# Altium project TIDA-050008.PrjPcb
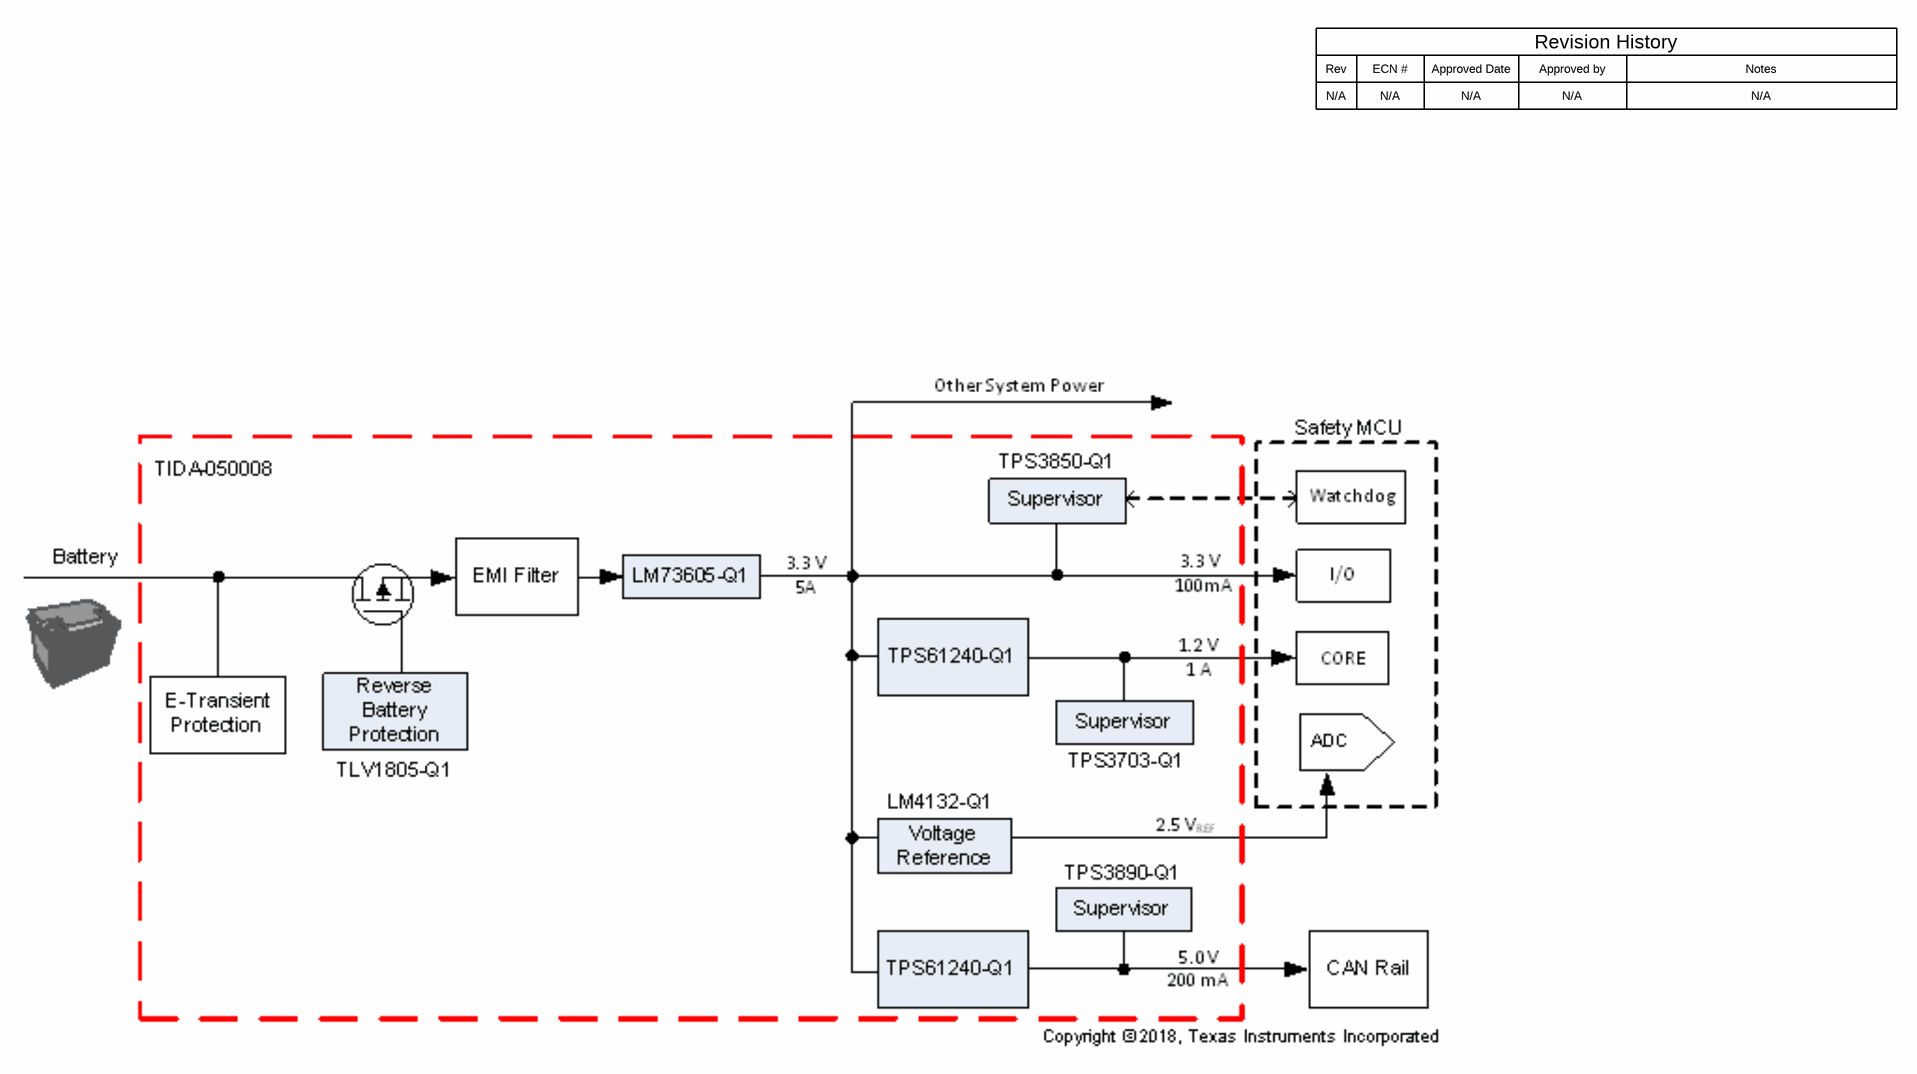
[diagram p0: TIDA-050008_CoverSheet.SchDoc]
TID: TIDA-050008; TechSupport: http://www.ti.com/support; SCH_Rev: E1; PRJ_Title: ADAS Reference Design with Improved Supervision; PRJ_Number: TIDA-050008; PRJ_Engineer: Ethan Than; PRJ_Customer: Public Release; PCB_Rev: E1; PCB_Layout: Ethan Than; CopyrightYear: 2018
6 sheets, 137 parts. Net scope: global (net labels, ports and power ports of the same name join across sheets).
Board file: TIDA-050008.PcbDoc
Sheets:
  TIDA-050008_CoverSheet.SchDoc
  TIDA-050008_Main Supply.SchDoc
  TIDA-050008_Watchdog and Vref.SchDoc
  TIDA-050008_CAN Supply and Supervisor.SchDoc
  TIDA-050008 Core Supply and Supervisor.SchDoc
  TIDA-050008_EVM_Hardware.SchDoc

## Sheet TIDA-050008_CoverSheet.SchDoc
size 431 x 279 mm; Date: Not shown in title block; ApprovedBy: Not shown in title block; CheckedBy: Not shown in title block; Author: Not shown in title block; CompanyName: Not shown in title block; Engineer: Not shown in title block; Organization: Not shown in title block; Address1: Not shown in title block; Address2: Not shown in title block; Address3: Not shown in title block; Address4: Not shown in title block; DocumentNumber: 1; Revision: Use project parameter SCH_Rev; SheetNumber: 1; SheetTotal: 6; PageSetup: Record=PageOptions¦CenterHorizontal=True¦CenterVertical=True¦PrintScale=1.00¦XCorrection=1.00¦YCorrection=1.00¦PrintKind=0¦BorderSize=5000000¦LeftOffset=0¦BottomOffset=0¦Orientation=2¦PaperLength=1000¦PaperWidth=1000¦Scale=100¦PaperSource=15¦PrintQuality=600¦MediaType=1¦DitherType=10¦PaperKind=Letter¦PrintScaleMode=1

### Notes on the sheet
- Rev
- N/A
- ECN #
- Approved Date
- Approved by
- Revision History
- Notes

## Sheet TIDA-050008_Main Supply.SchDoc
size 431 x 279 mm; Date: Not shown in title block; ApprovedBy: Not shown in title block; CheckedBy: Not shown in title block; Author: Not shown in title block; CompanyName: Not shown in title block; Engineer: Not shown in title block; Organization: Not shown in title block; Address1: Not shown in title block; Address2: Not shown in title block; Address3: Not shown in title block; Address4: Not shown in title block; DocumentNumber: 2; Revision: Use project parameter SCH_Rev; SheetNumber: 2; SheetTotal: 6; PageSetup: Record=PageOptions¦CenterHorizontal=True¦CenterVertical=True¦PrintScale=1.00¦XCorrection=1.00¦YCorrection=1.00¦PrintKind=0¦BorderSize=5000000¦LeftOffset=0¦BottomOffset=0¦Orientation=2¦PaperLength=1000¦PaperWidth=1000¦Scale=100¦PaperSource=15¦PrintQuality=600¦MediaType=1¦DitherType=10¦PaperKind=Letter¦PrintScaleMode=1
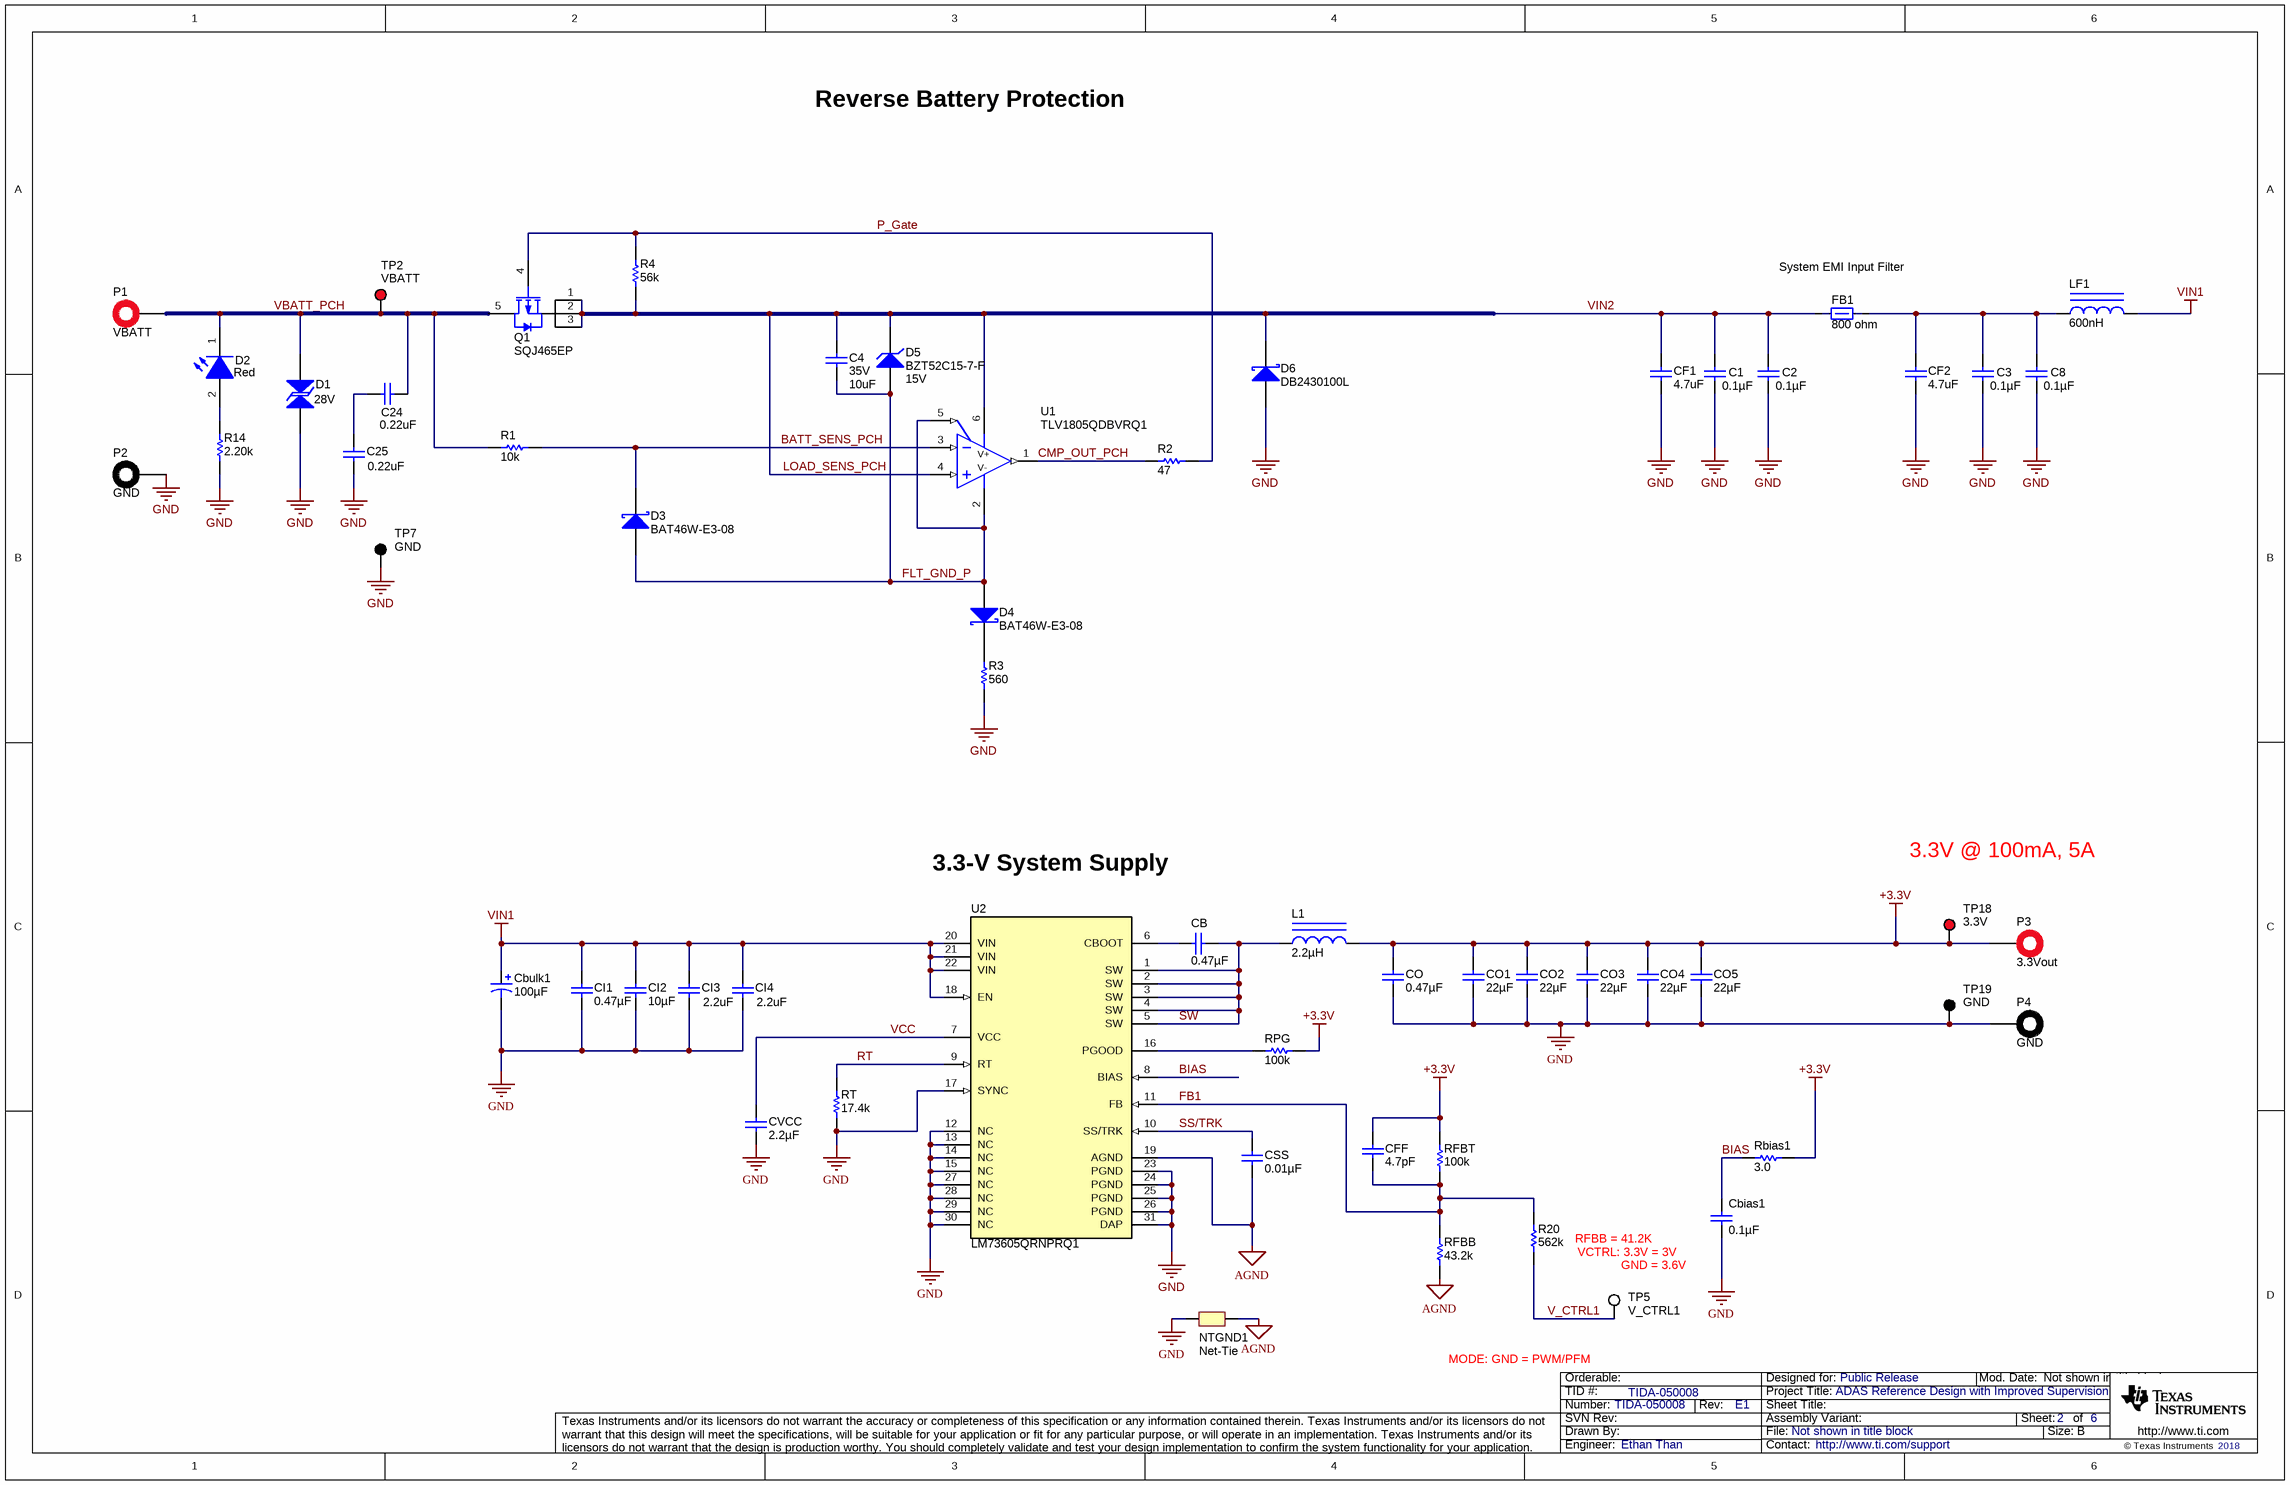
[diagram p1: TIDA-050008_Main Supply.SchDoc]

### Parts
C1  ValueDisplayed: 0.1µF  [0603S]  (hidden comment: GCM188R71C104KA37J)
C2  ValueDisplayed: 0.1µF  [0603S]  (hidden comment: GCM188R71C104KA37J)
C3  ValueDisplayed: 0.1µF  [0603S]  (hidden comment: GCM188R71C104KA37J)
C4  VDC_V: 35V  ValueDisplayed: 10uF  [1206_190]  (hidden comment: C3216X7R1V106M160AC)
C8  ValueDisplayed: 0.1µF  [0603S]  (hidden comment: GCM188R71C104KA37J)
C24  ValueDisplayed: 0.22uF  [0603L]  (hidden comment: CGA3E3X7R1H224K080AB)
C25  ValueDisplayed: 0.22uF  [0603L]  (hidden comment: CGA3E3X7R1H224K080AB)
CB  ValueDisplayed: 0.47µF  [0603L]  (hidden comment: GRM188R61E474KA12D)
Cbias1  ValueDisplayed: 0.1µF  [0603S]  (hidden comment: GCM188R71C104KA37J)
Cbulk1  ValueDisplayed: 100µF  [HXB_JA0]  (hidden comment: HHXB500ARA101MJA0G)
CF1  ValueDisplayed: 4.7uF  [1206_180]  (hidden comment: C3216X7R1H475K160AC)
CF2  ValueDisplayed: 4.7uF  [1206_180]  (hidden comment: C3216X7R1H475K160AC)
CFF  ValueDisplayed: 4.7pF  [0603]  (hidden comment: 06035A4R7CAT2A)
CI1  ValueDisplayed: 0.47µF  [0603]  (hidden comment: GRM21BR71H474KA88L)
CI2  ValueDisplayed: 10µF  [1210_270]  (hidden comment: GRM32ER71H106KA12L)
CI3  ValueDisplayed: 2.2uF  [0805L]  (hidden comment: C2012X5R1H225K125AB)
CI4  ValueDisplayed: 2.2uF  [0805L]  (hidden comment: C2012X5R1H225K125AB)
CO  ValueDisplayed: 0.47µF  [0805_HV]  (hidden comment: GRM21BR71H474KA88L)
CO1  ValueDisplayed: 22µF  [1210_270]  (hidden comment: GRM32ER71C226KE18L)
CO2  ValueDisplayed: 22µF  [1210_270]  (hidden comment: GRM32ER71C226KE18L)
CO3  ValueDisplayed: 22µF  [1210_270]  (hidden comment: GRM32ER71C226KE18L)
CO4  ValueDisplayed: 22µF  [1210_270]  (hidden comment: GRM32ER71C226KE18L)
CO5  ValueDisplayed: 22µF  [1210_270]  (hidden comment: GRM32ER71C226KE18L)
CSS  ValueDisplayed: 0.01µF  [0603]  (hidden comment: 06031C103MAT2A)
CVCC  ValueDisplayed: 2.2µF  [0603]  (hidden comment: GRM188C81A225KE34D)
D1  value 28V  [SMA]  (hidden comment: SMAJ28CA)
D2  value Red  [SML-P1_RED]  (hidden comment: SML-P12UTT86)
D3  BAT46W-E3-08  [SOD-123]
D4  BAT46W-E3-08  [SOD-123]
D5  BZT52C15-7-F  value 15V  [SOD-123]
D6  DB2430100L  [SOD-128]
FB1  ValueDisplayed: 800 ohm  [2220_390]  (hidden comment: HR2220V801R-10)
L1  ValueDisplayed: 2.2µH  [XAL5030]  (hidden comment: XAL5030-222MEB)
LF1  ValueDisplayed: 600nH  [XAL4020]  (hidden comment: XAL4020-601MEB)
NTGND1  Net-Tie  [Net-Tie_20milWide_60milLong]  (net tie, no BOM)
P1  VBATT  [6091]
P2  GND  [6092]
P3  3.3Vout  [6091]
P4  GND  [6092]
Q1  SQJ465EP  [PowerPAK_SO-8L]
R1  ValueDisplayed: 10k  [0402]  (hidden comment: ERJ-2GEJ103X)
R2  ValueDisplayed: 47  [0402]  (hidden comment: CRCW040247R0JNED)
R3  ValueDisplayed: 560  [1206]  (hidden comment: RC1206FR-07560RL)
R4  ValueDisplayed: 56k  [0603]  (hidden comment: RC0603JR-0756KL)
R14  ValueDisplayed: 2.20k  [0402L]  (hidden comment: CRCW04022K20FKED)
R20  ValueDisplayed: 562k  [0603]  (hidden comment: CRCW0603562KFKEA)
Rbias1  ValueDisplayed: 3.0  [0402S]  (hidden comment: CRCW04023R00JNED)
RFBB  ValueDisplayed: 43.2k  [0603]  (hidden comment: CRCW060343K2FKEA)
RFBT  ValueDisplayed: 100k  [0603]  (hidden comment: CRCW0603100KFKEA)
RPG  ValueDisplayed: 100k  [0603]  (hidden comment: CRCW0603100KFKEA)
RT  ValueDisplayed: 17.4k  [0603]  (hidden comment: CRCW060317K4FKEA)
TP2  VBATT  [Keystone5010]
TP5  V_CTRL1  [Keystone5012]
TP7  GND  [Keystone5011]
TP18  3.3V  [Keystone5010]
TP19  GND  [Keystone5011]
U1  TLV1805QDBVRQ1  [DBV0006A_N]
U2  LM73605QRNPRQ1  [RNP0030A]

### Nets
+3.3V: CFF.1 CO.2 CO1.1 CO2.1 CO3.1 CO4.1 CO5.1 L1.2 P3.1 Rbias1.2 RFBT.2 RPG.2 TP18.1
AGND: CSS.2 NTGND1.2 RFBB.1 U2.19(AGND)
GND: C1.2 C2.2 C3.2 C8.2 C25.2 Cbias1.2 Cbulk1.2(-) CF1.2 CF2.2 CI1.1 CI2.1 CI3.2 CI4.2 CO.1 CO1.2 CO2.2 CO3.2 CO4.2 CO5.2 CVCC.2 D1.2 D6.2(A) NTGND1.1 P2.1 P4.1 R3.1 R14.1 RT.2 TP7.1 TP19.1 U2.12(NC) U2.13(NC) U2.14(NC) U2.15(NC) U2.17(SYNC) U2.23(PGND) U2.24(PGND) U2.25(PGND) U2.26(PGND) U2.27(NC) U2.28(NC) U2.29(NC) U2.30(NC) U2.31(DAP)
VIN1: Cbulk1.1(+) CI1.2 CI2.2 CI3.1 CI4.1 LF1.2 U2.18(EN) U2.20(VIN) U2.21(VIN) U2.22(VIN)
BATT_SENS_PCH: D3.1(K) R1.1 U1.3(IN-)
BIAS: Cbias1.1 Rbias1.1 U2.8(BIAS)
CMP_OUT_PCH: R2.1 U1.1(OUT)
FB1: CFF.2 R20.2 RFBB.2 RFBT.1 U2.11(FB)
FLT_GND_P: C4.2 D3.2(A) D4.2(A) D5.2(A) U1.2(V-) U1.5(SD)
LOAD_SENS_PCH: C1.1 C2.1 C4.1 CF1.1 D5.1(K) D6.1(K) FB1.1 Q1.1(S) Q1.2(S) Q1.3(S) R4.1 U1.4(IN+) U1.6(V+)  [also labelled VIN2]
P_Gate: Q1.4(G) R2.2 R4.2
RT: RT.1 U2.9(RT)
SS/TRK: CSS.1 U2.10(SS/TRK)
SW: CB.2 L1.1 U2.1(SW) U2.2(SW) U2.3(SW) U2.4(SW) U2.5(SW)
V_CTRL1: R20.1 TP5.1
VBATT_PCH: C24.2 D1.1 D2.1(K) P1.1 Q1.5(D) R1.2 TP2.1
VCC: CVCC.1 U2.7(VCC)
NetC3_1: C3.1 C8.1 CF2.1 FB1.2 LF1.1
NetC24_1: C24.1 C25.1
NetCB_1: CB.1 U2.6(CBOOT)
NetD2_2: D2.2(A) R14.2
NetD4_1: D4.1(K) R3.2
NetRPG_1: RPG.1 U2.16(PGOOD)

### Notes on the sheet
- Reverse Battery Protection
- (near FB1) System EMI Input Filter
- 3.3-V System Supply
- 3.3V @ 100mA, 5A
- RFBB = 41.2K
- VCTRL: 3.3V = 3V
- GND = 3.6V
- MODE: GND = PWM/PFM

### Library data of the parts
C1-C3 C8 = GCM188R71C104KA37J: CAP, CERM, 0.1 µF, 16 V, +/- 10%, X7R, AEC-Q200 Grade 1, 0603; Manufacturer: MuRata; Polarized: N; CompType: Capacitor; Value: 0.1uF; U/M: EA; Cap_F: 0.0000001; Tolerance_%: 10; Value1: Unknown; VDC_V: 16; Value2: 16V; TaMin_C: -55; TaMax_C: 125; Cap_Case: 0603; AEC Category: Q200; AEC Qualified: Y; AEC Grade: 1; SizeArea_mm2: 1.28; SizeAreaWB_mm2: 4.68; SizeX_mm: 1.6; SizeY_mm: 0.8
C4 = CMP-0008706-2: CAP, CERM, 10 uF, 35 V, +/- 20%, X7R, 1206_190; Manufacturer: TDK; TaMin_C: -55°C; Polarized: N; SizeAreaWB_mm2: 10.92; Value1: Unknown; U/M: EA; Value: 10uF; TaMax_C: 125°C; SizeZ_mm: 1.9; SizeX_mm: 3.2; SizeY_mm: 1.6; Cap_Case: 1206; SizeArea_mm2: 5.12; CompType: Capacitor; Cap_F: 10µF; AEC Category: Q200
C24 C25 = CMP-0007094-5: CAP, CERM, 0.22 uF, 50 V, +/- 10%, X7R, AEC-Q200 Grade 1, 0603; Manufacturer: TDK; TaMin_C: -55°C; ESR_ohm: 0.021699; Polarized: N; SizeAreaWB_mm2: 4.68; Value1: 0.021699 ohm; U/M: EA; Value: 0.22uF; TaMax_C: 125°C; SizeZ_mm: 1; SizeX_mm: 1.6; SizeY_mm: 0.8; Cap_Case: 0603; Value2: 50V; SizeArea_mm2: 1.28; CompType: Capacitor; AEC Qualified: Y; Cap_F: 220nF; IRMS_A: 1.12496A; AEC Category: Q200
CB = GRM188R61E474KA12D: CAP, CERM, 0.47uF, 25V, +/-10%, X5R, 0603; Manufacturer: MuRata; Polarized: N; CompType: Capacitor; U/M: EA; Cap_F: 0.00000047; Tolerance_%: 10; Value1: Unknown; VDC_V: 25; TaMin_C: -55; TaMax_C: 85; Cap_Case: 0603
Cbias1 = GCM188R71C104KA37J: CAP, CERM, 0.1 µF, 16 V, +/- 10%, X7R, AEC-Q200 Grade 1, 0603; Manufacturer: MuRata; Polarized: N; CompType: Capacitor; Value: 0.1uF; U/M: EA; Cap_F: 0.0000001; Tolerance_%: 10; Value1: Unknown; VDC_V: 16; Value2: 16V; TaMin_C: -55; TaMax_C: 125; Cap_Case: 0603; AEC Category: Q200; AEC Qualified: Y; AEC Grade: 1
Cbulk1 = HHXB500ARA101MJA0G: CAP, Aluminum Polymer, 100 µF, 50 V, +/- 20%, 0.025 ohm, AEC-Q200 Grade 2, D10xL10mm SMD; Manufacturer: Chemi-Con; Polarized: Y; CompType: Capacitor; Value: 100uF; U/M: EA; Cap_F: 0.0001; Tolerance_%: 20; VDC_V: 50; Value2: 50V; ESR_ohm: 0.025; IRMS_A: 2; TaMin_C: -55; TaMax_C: 105; Cap_Case: 10x10mm; AEC Category: Q200
CF1 CF2 = CMP-0008702-2: CAP, CERM, 4.7 uF, 50 V, +/- 10%, X7R, 1206; Manufacturer: TDK; TaMin_C: -55°C; ESR_ohm: 3.158m; Polarized: N; SizeAreaWB_mm2: 10.92; Value1: 0.003158 ohm; U/M: EA; Value: 4.7uF; TaMax_C: 125°C; SizeZ_mm: 1.8; SizeX_mm: 3.2; SizeY_mm: 1.6; Value2: 50V; SizeArea_mm2: 5.12; CompType: Capacitor; Cap_F: 4.7µF; IRMS_A: 4.08379A; AEC Category: Q200
CFF = 06035A4R7CAT2A: CAP, CERM, 4.7 pF, 50 V, +/- 5%, C0G/NP0, 0603; Manufacturer: AVX; Polarized: N; CompType: Capacitor; Value: 4.7pF; U/M: EA; Cap_F: 0.0000000000047; Tolerance_%: 5; ESR_ohm: 0.633; Value1: 0.633 ohm; VDC_V: 50; Value2: 50V; TaMin_C: -55; TaMax_C: 125; AEC Category: Q200
CI1 = GRM21BR71H474KA88L: CAP, CERM, 0.47 µF, 50 V, +/- 10%, X7R, 0805; Manufacturer: MuRata; Polarized: N; CompType: Capacitor; Value: 0.47uF; U/M: EA; Cap_F: 0.00000047; Tolerance_%: 10; Value1: Unknown; VDC_V: 50; Value2: 50V; TaMin_C: -55; TaMax_C: 125; Cap_Case: 0805; SizeArea_mm2: 2.5; SizeAreaWB_mm2: 6.75; SizeX_mm: 2; SizeY_mm: 1.25; SizeZ_mm: 1.45; AEC Category: Q200
CI2 = GRM32ER71H106KA12L: CAP, CERM, 10 µF, 50 V, +/- 10%, X7R, 1210; Manufacturer: MuRata; Polarized: N; CompType: Capacitor; Value: 10uF; U/M: EA; Cap_F: 0.00001; Tolerance_%: 10; Value1: Unknown; VDC_V: 50; Value2: 50V; TaMin_C: -55; TaMax_C: 125; Cap_Case: 1210; SizeArea_mm2: 8; SizeAreaWB_mm2: 14.7; SizeX_mm: 3.2; SizeY_mm: 2.5; SizeZ_mm: 2.7; AEC Category: Q200
CI3 CI4 = CMP-0007836-2: CAP, CERM, 2.2 uF, 50 V, +/- 10%, X5R, 0805; Manufacturer: TDK; TaMin_C: -55°C; ESR_ohm: 3.66m; Polarized: N; SizeAreaWB_mm2: 6.75; Value1: 0.00366 ohm; U/M: EA; Value: 2.2uF; TaMax_C: 85°C; SizeZ_mm: 1.45; SizeX_mm: 2; SizeY_mm: 1.25; Cap_Case: 0805; Value2: 50V; SizeArea_mm2: 2.5; CompType: Capacitor; Cap_F: 2.2µF; IRMS_A: 3.41207A; AEC Category: Q200
CO = GRM21BR71H474KA88L: CAP, CERM, 0.47 µF, 50 V, +/- 10%, X7R, 0805; Manufacturer: MuRata; Polarized: N; CompType: Capacitor; Value: 0.47uF; U/M: EA; Cap_F: 0.00000047; Tolerance_%: 10; Value1: Unknown; VDC_V: 50; Value2: 50V; TaMin_C: -55; TaMax_C: 125; Cap_Case: 0805
CO1-CO5 = GRM32ER71C226KE18L: CAP, CERM, 22 µF, 16 V, +/- 10%, X7R, 1210; Manufacturer: MuRata; Polarized: N; CompType: Capacitor; Value: 22uF; U/M: EA; Cap_F: 0.000022; Tolerance_%: 10; ESR_ohm: 0.003; Value1: 0.003 ohm; VDC_V: 16; Value2: 16V; TaMin_C: -55; TaMax_C: 125; Cap_Case: 1210; AEC Category: Q200; SizeArea_mm2: 8; SizeAreaWB_mm2: 14.7; SizeX_mm: 3.2; SizeY_mm: 2.5; SizeZ_mm: 2.7
CSS = 06031C103MAT2A: CAP, CERM, 0.01 µF, 100 V, +/- 20%, X7R, 0603; Manufacturer: AVX; Polarized: N; CompType: Capacitor; Value: 0.01uF; U/M: EA; Cap_F: 0.00000001; Tolerance_%: 20; ESR_ohm: 0.098; Value1: 0.098 ohm; VDC_V: 100; Value2: 100V; TaMin_C: -55; TaMax_C: 125
CVCC = GRM188C81A225KE34D: CAP, CERM, 2.2uF, 10V, +/-10%, X6S, 0603; Manufacturer: MuRata; Polarized: N; CompType: Capacitor; U/M: EA; Cap_F: 0.0000022; Tolerance_%: 10; Value1: Unknown; TaMin_C: -55; TaMax_C: 105
D1 = CMP-0005456-2: Diode, TVS, Bi, 28 V, SMA; Manufacturer: Littelfuse; Power_W: 3.3W; SizeAreaWB_mm2: 37.3428; RJA_CperW: 120; U/M: EA; SizeZ_mm: 2.87; SizeX_mm: 5.59; SizeY_mm: 2.92; SizeArea_mm2: 16.3228; AEC Category: Q101
D2 = CMP-0002872-1: LED, Red, SMD; Manufacturer: Rohm; Io_A: 20mA; Value1: W; U/M: EA; Vf_V: 2V; Type: AlInGaP
D3 D4 = CMP-0080760-1: Diode, Schottky, 100 V, 0.15 A, AEC-Q101, SOD-123; Manufacturer: Vishay-Semiconductor; Io_A: 1.5dA; SizeAreaWB_mm2: 13.095; Vr_V: 100V; Value1: 0.15A; TJmax_C: 125°C; Value: 100V; SizeZ_mm: 1.35; SizeX_mm: 3.85; SizeY_mm: 1.7; Vf_V: 1V; SizeArea_mm2: 6.545; AEC Qualified: Y; AEC Category: Q101
D5 = CMP-0005768-2: Diode, Zener, 15 V, 370 mW, AEC-Q101, SOD-123; Manufacturer: Diodes Inc.; Power_W: 370mW; SizeAreaWB_mm2: 13.095; Value1: 0.37W; RJA_CperW: 338; U/M: EA; SizeZ_mm: 1.35; SizeX_mm: 3.85; SizeY_mm: 1.7; SizeArea_mm2: 6.545; AEC Qualified: Y; AEC Category: Q101
D6 = CMP-0028872-2: Diode, Schottky, 30 V, 2 A, SOD-128; Manufacturer: Panasonic; Io_A: 2A; Green_Lifecycle: Not Set; SizeAreaWB_mm2: 19.6; Vr_V: 30V; Green_REACh: Incomplete; TJmax_C: 150°C; U/M: EA; Value: 30V; SizeZ_mm: 1.1; SizeX_mm: 4.6; SizeY_mm: 2.5; Vf_V: 3.9dV; Value2: 0.39V; SizeArea_mm2: 11.5; AEC Qualified: N; AEC Category: Q101
FB1 = HR2220V801R-10: Ferrite Bead, 800 ohm @ 100 MHz, 8 A, 2220; Manufacturer: Laird-Signal Integrity Products; Value: 800 ohm; Imax_A: 8; DCR_ohm: 0.01; Value1: 0.01 ohm; Value2: 8A; ZTyp@100MHz_Ohm: 800; Ztyp@1GHz_Ohm: 75; SizeAreaWB_mm2: 53.96; SizeArea_mm2: 28.56; SizeX_mm: 5.6; SizeY_mm: 5.1; SizeZ_mm: 3.9
L1 = XAL5030-222MEB: Inductor, Shielded, Composite, 2.2 µH, 9.2 A, 0.01 ohm, SMD; Manufacturer: Coilcraft; Value: 2.2uH; Ind_H: 2.2E-6; Imax_A: 9.2; Irms: 9.2A @ 40C rise; Isat: 12.9A @ 30% inductance drop; DCR_ohm: 0.01; Value2: 9.2A; AEC Category: Q200; SizeAreaWB_mm2: 54.4544; SizeArea_mm2: 28.9344; SizeX_mm: 5.28; SizeY_mm: 5.48; SizeZ_mm: 3.1
LF1 = CMP-0060988-1: Inductor, Shielded, Composite, 600 nH, 10.38 A, 0.01 ohm, SMD; Manufacturer: Coilcraft; Isat: 10.38A @ 30% inductance drop; Irms: 11.7A @ 40C rise; Green_Lifecycle: Not Set; SizeAreaWB_mm2: 28.09; DCR_ohm: 0.01; Green_REACh: Incomplete; Value: 600nH; Imax_A: 10.38A; SizeZ_mm: 2.1; SizeX_mm: 4.3; SizeArea_mm2: 18.49; AEC Category: Q200
NTGND1 = Net-Tie: Single point connection between nets.; SymbolCreator: codlsc
P1 P3 = 6091: Standard Banana Jack, Insulated, Red; Manufacturer: Keystone; SymbolCreator: a0412235; CompType: Connector; U/M: EA
P2 P4 = 6092: Standard Banana Jack, Insulated, Black; Manufacturer: Keystone; SymbolCreator: a0412235; CompType: Connector; U/M: EA
Q1 = CMP-0000140-2: MOSFET, P-CH, -60 V, -30 A, PowerPAK_SO-8L; PartNumber: SQJ461EP; Alternate Manufacturer: None; Manufacturer: Vishay-Siliconix; SizeZ_mm: 1.14; ChType: P; Value2: 90 nC; Value1: 0.03; VdsMax_V: -60V; SizeX_mm: 6.15; SizeY_mm: 5.13; Vgs_V: -20V; Value: -60V; Rdson45_ohm: 0.031; SizeArea_mm2: 31.5495; AEC Category: Q101; IdsMax_A: -30A; SizeAreaWB_mm2: 58.1095; U/M: EA; QgTyp_nC: 90
R1 = CMP-0026994-4: RES, 10 k, 5%, 0.1 W, AEC-Q200 Grade 0, 0402; Manufacturer: Panasonic; Power_W: 100mW; TempCo: 200 ppm/C; Value_Code: 10k0; U/M: EA; Value: 10k; EIA_Code: E24; SizeX_mm: 1; SizeY_mm: 0.5; SizeZ_mm: 0.6; Value2: 0.1W; AEC Qualified: Y; VDC_V: 50V; AEC Grade: 0; AEC Category: Q200
R2 = CMP-0026936-3: RES, 47, 5%, 0.063 W, AEC-Q200 Grade 0, 0402; Manufacturer: Vishay-Dale; Power_W: 63mW; TempCo: 200 ppm/C; Value_Code: 47R0; Value: 47; EIA_Code: E24; SizeX_mm: 1; SizeY_mm: 0.5; SizeZ_mm: 0.6; Value2: 0.063W; CompType: Resistor; AEC Qualified: Y; VDC_V: 50V; AEC Category: Q200; AEC Grade: 0
R3 = CMP-0018374-2: RES, 560, 1%, 0.25 W, 1206; Manufacturer: Yageo America; Power_W: 250mW; TempCo: 100 ppm/C; Value_Code: 560R; U/M: EA; Value: 560; SizeX_mm: 3.2; SizeY_mm: 1.6; SizeZ_mm: 1.35; Value2: 0.25W; SizeArea_mm2: 5.12; CompType: Resistor; VDC_V: 200V; AEC Category: Q200
R4 = CMP-0025931-5: RES, 56 k, 5%, 0.1 W, 0603; Manufacturer: Yageo; Power_W: 100mW; TempCo: 100 ppm/C; Value_Code: 56k0; Value: 56k; EIA_Code: E24; SizeX_mm: 1.6; SizeY_mm: 0.8; SizeZ_mm: 1; Value2: 0.1W; SizeArea_mm2: 1.28; CompType: Resistor; AEC Qualified: N; VDC_V: 75V; AEC Category: Q200; SizeAreaWB_mm2: 4.68
R14 = CMP-0026231-2: RES, 2.20 k, 1%, 0.063 W, AEC-Q200 Grade 0, 0402; Manufacturer: Vishay-Dale; Power_W: 63mW; TempCo: 100 ppm/C; Value_Code: 2k20; Value: 2.20k; Res_ohm: 2.2k; SizeX_mm: 1; SizeY_mm: 0.5; SizeZ_mm: 0.6; Value2: 0.063W; CompType: Resistor; AEC Qualified: Y; AEC Category: Q200; AEC Grade: 0
R20 = CMP-0022497-4: RES, 562 k, 1%, 0.1 W, AEC-Q200 Grade 0, 0603; Manufacturer: Vishay-Dale; Value: 562k; Power_W: 100mW; Value2: 0.1W; VDC_V: 75V; TempCo: 100 ppm/C; SizeArea_mm2: 1.28; SizeX_mm: 1.6; SizeY_mm: 0.8; SizeZ_mm: 1; EIA_Code: E96; AEC Category: Q200; AEC Qualified: Y; AEC Grade: 0
Rbias1 = CRCW04023R00JNED: RES, 3.0, 5%, 0.063 W, 0402; Manufacturer: Vishay-Dale; CompType: Resistor; Value: 3.0; Res_ohm: 3; Value_Code: 3R00; Tolerance_%: 5; Power_W: 0.063; Value2: 0.063W; VDC_V: 50; TempCo: 200 ppm/C; EIA_Code: E24; U/M: EA; AEC Category: Q200
RFBB = CMP-0022422-4: RES, 43.2 k, 1%, 0.1 W, AEC-Q200 Grade 0, 0603; Manufacturer: Vishay-Dale; Value: 43.2k; Value_Code: 43k2; Power_W: 100mW; Value2: 0.1W; VDC_V: 75V; TempCo: 100 ppm/C; EIA_Code: E96; AEC Category: Q200; AEC Qualified: Y; AEC Grade: 0; SizeArea_mm2: 1.28; SizeX_mm: 1.6; SizeY_mm: 0.8; SizeZ_mm: 1
RFBT = CMP-0021990-4: RES, 100 k, 1%, 0.1 W, AEC-Q200 Grade 0, 0603; Manufacturer: Vishay-Dale; CompType: Resistor; Value: 100k; Power_W: 100mW; Value2: 0.1W; VDC_V: 75V; TempCo: 100 ppm/C; SizeArea_mm2: 1.28; SizeX_mm: 1.6; SizeY_mm: 0.8; SizeZ_mm: 1; EIA_Code: E96; AEC Category: Q200; AEC Qualified: Y; AEC Grade: 0
RPG = CRCW0603100KFKEA: RES, 100 k, 1%, 0.1 W, 0603; Manufacturer: Vishay-Dale; CompType: Resistor; Value: 100k; Res_ohm: 100000; Tolerance_%: 1; Power_W: 0.1; Value2: 0.1W; VDC_V: 75; TempCo: 100 ppm/C; EIA_Code: E96; U/M: EA
RT = CRCW060317K4FKEA: RES, 17.4 k, 1%, 0.1 W, 0603; Manufacturer: Vishay-Dale; CompType: Resistor; Value: 17.4k; Res_ohm: 17400; Value_Code: 17k4; Tolerance_%: 1; Power_W: 0.1; Value2: 0.1W; VDC_V: 75; TempCo: 100 ppm/C; EIA_Code: E96; U/M: EA
TP2 TP18 = CMP-0055147-1: Test Point, Multipurpose, Red, TH; Manufacturer: Keystone; PartNumber: 5010; CNHeader: FALSE; Green_Lifecycle: Active; Green_REACh: Passed; ContactFinish: Silver; CT: TRUE
TP5 = CMP-0055149-1: Test Point, Multipurpose, White, TH; Manufacturer: Keystone; PartNumber: 5012; CNHeader: FALSE; Green_Lifecycle: Active; Green_REACh: Passed; ContactFinish: Silver; CT: TRUE
TP7 TP19 = CMP-0055148-1: Test Point, Multipurpose, Black, TH; Manufacturer: Keystone; CNHeader: FALSE; Green_Lifecycle: Active; Green_REACh: Passed; ContactFinish: Silver; CT: TRUE
U1 = CMP-0080758-2: Automotive 40-V, microPower, Push-Pull Comparator with Shutdown, DBV0006A (SOT-23-6); Alternate Manufacturer: Texas Instruments; SizeAreaWB_mm2: 14.82; SizeZ_mm: 1.45; SizeX_mm: 2.8; SizeY_mm: 2.9; SizeArea_mm2: 8.12; CompType: IC; AEC Qualified: Y; AEC Category: Q200
U2 = CMP-0013936-4: Automotive 3.5V to 36V 5A Synchronous Step-Down Voltage Regulator, RNP0030A (WQFN-30); Manufacturer: Texas Instruments; Alternate PartNumber: LM73605QRNPTQ1; SizeX_mm: 4; SizeY_mm: 6; CompType: IC; SizeZ_mm: 0.8; SizeArea_mm2: 24; SizeAreaWB_mm2: 48; AEC Category: Q200; AEC Qualified: Y

## Sheet TIDA-050008_Watchdog and Vref.SchDoc
size 431 x 279 mm; Date: Not shown in title block; ApprovedBy: Not shown in title block; CheckedBy: Not shown in title block; Author: Not shown in title block; CompanyName: Not shown in title block; Engineer: Not shown in title block; Organization: Not shown in title block; Address1: Not shown in title block; Address2: Not shown in title block; Address3: Not shown in title block; Address4: Not shown in title block; DocumentNumber: 3; Revision: Use project parameter SCH_Rev; SheetNumber: 3; SheetTotal: 6; PageSetup: Record=PageOptions¦CenterHorizontal=True¦CenterVertical=True¦PrintScale=1.00¦XCorrection=1.00¦YCorrection=1.00¦PrintKind=0¦BorderSize=5000000¦LeftOffset=0¦BottomOffset=0¦Orientation=2¦PaperLength=1000¦PaperWidth=1000¦Scale=100¦PaperSource=15¦PrintQuality=600¦MediaType=1¦DitherType=10¦PaperKind=Letter¦PrintScaleMode=1
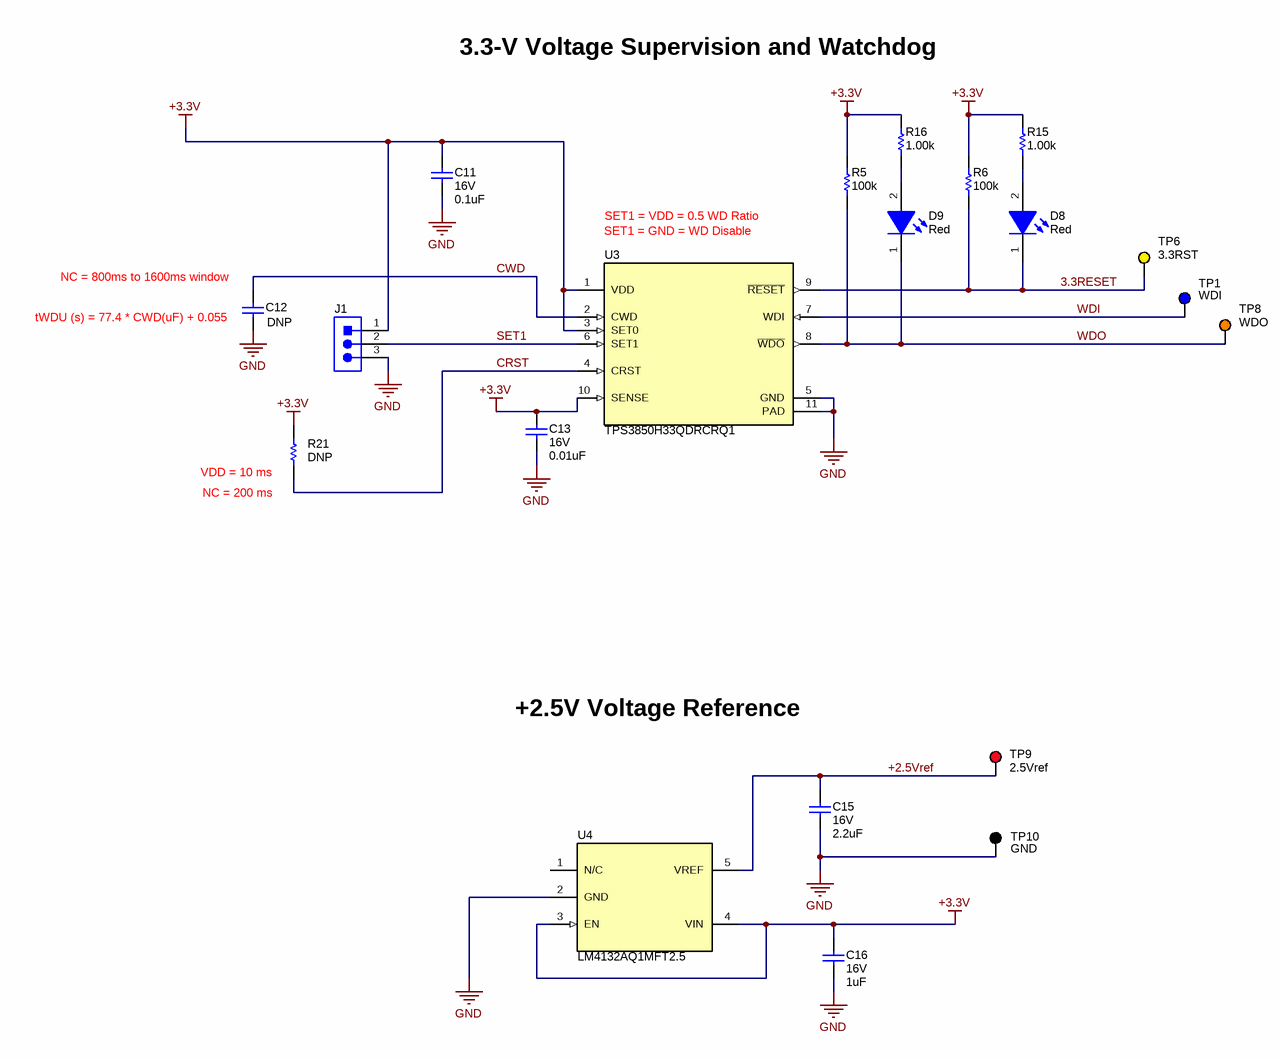
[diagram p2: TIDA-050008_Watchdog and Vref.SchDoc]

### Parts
C11  VDC_V: 16V  ValueDisplayed: 0.1uF  [0603]  (hidden comment: GRM188R71C104KA01D)
C12  DNP  [0603]
C13  VDC_V: 16V  ValueDisplayed: 0.01uF  [0603]  (hidden comment: GRM188R71C103KA01D)
C15  VDC_V: 16V  ValueDisplayed: 2.2uF  [0603]  (hidden comment: GRM188Z71C225KE43)
C16  VDC_V: 16V  ValueDisplayed: 1uF  [0603]  (hidden comment: GCM188R71C105KA64D)
D8  value Red  [SML-P1_RED]  (hidden comment: SML-P12UTT86)
D9  value Red  [SML-P1_RED]  (hidden comment: SML-P12UTT86)
J1  PEC03SAAN  [CONN_PEC03SAAN]  (value not drawn)
R5  ValueDisplayed: 100k  [0603]  (hidden comment: CRCW0603100KFKEA)
R6  ValueDisplayed: 100k  [0603]  (hidden comment: CRCW0603100KFKEA)
R15  ValueDisplayed: 1.00k  [0402]  (hidden comment: CRCW04021K00FKED)
R16  ValueDisplayed: 1.00k  [0402]  (hidden comment: CRCW04021K00FKED)
R21  DNP  [0603]
TP1  WDI  [Keystone5127]
TP6  3.3RST  [Keystone5014]
TP8  WDO  [Keystone5013]
TP9  2.5Vref  [Keystone5010]
TP10  GND  [Keystone5011]
U3  TPS3850H33QDRCRQ1  [DRC0010R]
U4  LM4132AQ1MFT2.5  [DBV0005A_N]

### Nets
+3.3V: C11.1 C13.1 C16.1 J1.1 R5.2 R6.2 R15.1 R16.1 R21.2 U3.1(VDD) U3.3(SET0) U3.10(SENSE) U4.3(EN) U4.4(VIN)
GND: C11.2 C12.2 C13.2 C15.2 C16.2 J1.3 TP10.1 U3.5(GND) U3.11(PAD) U4.2(GND)
3.3RESET: D8.1(K) R6.1 TP6.1 U3.9(~{RESET})
+2.5Vref: C15.1 TP9.1 U4.5(VREF)
CRST: R21.1 U3.4(CRST)
CWD: C12.1 U3.2(CWD)
SET1: J1.2 U3.6(SET1)
WDI: TP1.1 U3.7(WDI)
WDO: D9.1(K) R5.1 TP8.1 U3.8(~{WDO})
NetD8_2: D8.2(A) R15.2
NetD9_2: D9.2(A) R16.2

Not connected (* = marked no-connect by the designer): U4 1(N/C)

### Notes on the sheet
- 3.3-V Voltage Supervision and Watchdog
- (near U3) SET1 = GND = WD Disable
- SET1 = VDD = 0.5 WD Ratio
- (near C12) NC = 800ms to 1600ms window
- (near C12) tWDU (s) = 77.4 * CWD(uF) + 0.055
- (near R21) VDD = 10 ms
- (near R21) NC = 200 ms
- +2.5V Voltage Reference

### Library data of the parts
C11 = CMP-0007378-5: CAP, CERM, 0.1 uF, 16 V, +/- 10%, X7R, 0603; Manufacturer: MuRata; TaMin_C: -55°C; Polarized: N; SizeAreaWB_mm2: 4.68; Value1: Unknown; U/M: EA; Value: 0.1uF; TaMax_C: 125°C; SizeZ_mm: 1; SizeX_mm: 1.6; SizeY_mm: 0.8; SizeArea_mm2: 1.28; AEC Category: Q200; Cap_F: 100nF
C12 = CMP-0007378-5: CAP, CERM, 0.1 uF, 16 V, +/- 10%, X7R, 0603; Manufacturer: MuRata; PartNumber: GRM188R71C104KA01D; TaMin_C: -55°C; Polarized: N; SizeAreaWB_mm2: 4.68; Value1: Unknown; U/M: EA; Value: 0.1uF; TaMax_C: 125°C; SizeZ_mm: 1; SizeX_mm: 1.6; SizeY_mm: 0.8; Value2: 16V; SizeArea_mm2: 1.28; CompType: Capacitor; AEC Category: Q200; Cap_F: 100nF
C13 = CMP-0007377-4: CAP, CERM, 0.01 uF, 16 V, +/- 10%, X7R, 0603; Manufacturer: MuRata; TaMin_C: -55°C; Polarized: N; SizeAreaWB_mm2: 4.68; Value1: Unknown; U/M: EA; Value: 0.01uF; TaMax_C: 125°C; SizeZ_mm: 1; SizeX_mm: 1.6; SizeY_mm: 0.8; SizeArea_mm2: 1.28; Cap_F: 10nF; AEC Category: Q200
C15 = CMP-0007499-4: CAP, CERM, 2.2 uF, 16 V, +/- 10%, X7R, 0603; Manufacturer: MuRata; TaMin_C: -55°C; Polarized: N; SizeAreaWB_mm2: 4.68; Value1: Unknown; U/M: EA; Value: 2.2uF; TaMax_C: 125°C; SizeZ_mm: 1; SizeX_mm: 1.6; SizeY_mm: 0.8; SizeArea_mm2: 1.28; AEC Category: Q200; Cap_F: 2.2µF
C16 = CMP-0007136-5: CAP, CERM, 1 uF, 16 V, +/- 10%, X7R, AEC-Q200 Grade 1, 0603; Manufacturer: MuRata; TaMin_C: -55°C; Polarized: N; SizeAreaWB_mm2: 4.68; Value1: Unknown; U/M: EA; Value: 1uF; TaMax_C: 125°C; SizeZ_mm: 1; SizeX_mm: 1.6; SizeY_mm: 0.8; SizeArea_mm2: 1.28; AEC Qualified: Y; AEC Category: Q200; Cap_F: 1µF
D8 D9 = CMP-0002872-1: as D2 on sheet TIDA-050008_Main Supply
J1 = CMP-0002338-1: Header, 100mil, 3x1, Tin, TH; Manufacturer: Sullins Connector Solutions; CNHeader: TRUE; Current_A: 3A; Green_Lifecycle: Not Set; Shrouded: N; Gender: Male; Green_REACh: Incomplete; Voltage_V: 1.8kV; Row_Count: 1; Pitch_mm: 2.54; CT: FALSE; Cert_UL: Y
R5 R6 = CMP-0021990-4: RES, 100 k, 1%, 0.1 W, AEC-Q200 Grade 0, 0603; Manufacturer: Vishay-Dale; Value: 100k; Power_W: 100mW; Value2: 0.1W; VDC_V: 75V; TempCo: 100 ppm/C; SizeArea_mm2: 1.28; SizeX_mm: 1.6; SizeY_mm: 0.8; SizeZ_mm: 1; EIA_Code: E96; AEC Category: Q200; AEC Qualified: Y; AEC Grade: 0
R15 R16 = CMP-0026071-3: RES, 1.00 k, 1%, 0.063 W, AEC-Q200 Grade 0, 0402; Manufacturer: Vishay-Dale; Power_W: 63mW; TempCo: 100 ppm/C; Value_Code: 1k00; Value: 1.00k; Res_ohm: 1k; SizeX_mm: 1; SizeY_mm: 0.5; SizeZ_mm: 0.6; Value2: 0.063W; AEC Qualified: Y; AEC Category: Q200; AEC Grade: 0; EIA_Code: E96; VDC_V: 50V
R21 = CMP-0021998-4: RES, 10.0 k, 1%, 0.1 W, AEC-Q200 Grade 0, 0603; PartNumber: CRCW060310K0FKEA; Manufacturer: Vishay-Dale; CompType: Resistor; Value: 10.0k; Res_ohm: 10k; Value_Code: 10k0; Power_W: 100mW; Value2: 0.1W; VDC_V: 75V; TempCo: 100 ppm/C; SizeArea_mm2: 1.28; SizeX_mm: 1.6; SizeY_mm: 0.8; SizeZ_mm: 1; EIA_Code: E96; AEC Category: Q200; AEC Qualified: Y; AEC Grade: 0
TP1 = CMP-0055156-1: Test Point, Multipurpose, Blue, TH; Manufacturer: Keystone; CNHeader: FALSE; Green_Lifecycle: Active; Green_REACh: Passed; ContactFinish: Silver; CT: TRUE
TP6 = CMP-0055151-1: Test Point, Multipurpose, Yellow, TH; Manufacturer: Keystone; PartNumber: 5014; CNHeader: FALSE; Green_Lifecycle: Active; Green_REACh: Passed; ContactFinish: Silver; CT: TRUE
TP8 = CMP-0055150-1: Test Point, Multipurpose, Orange, TH; Manufacturer: Keystone; PartNumber: 5013; CNHeader: FALSE; Green_Lifecycle: Active; Green_REACh: Passed; ContactFinish: Silver; CT: TRUE
TP9 = CMP-0055147-1: as TP2 on sheet TIDA-050008_Main Supply
TP10 = CMP-0055148-1: as TP7 on sheet TIDA-050008_Main Supply
U3 = CMP-0081417-2: Automotive Precision Voltage Supervisor With Programmable Window Watchdog Timer, DRC0010R (VSON-10); Alternate Manufacturer: Texas Instruments; SizeAreaWB_mm2: 16; SizeZ_mm: 1; SizeX_mm: 3; SizeArea_mm2: 9; CompType: IC; AEC Qualified: Y; AEC Category: Q200
U4 = CMP-0081400-1: Automotive SOT23 Precision Low Dropout Voltage Reference, DBV0005A (SOT-23-5); Alternate PartNumber: LM4132AQ1MFR2.5; Alternate Manufacturer: Texas Instruments; SizeAreaWB_mm2: 14.82; SizeZ_mm: 1.45; SizeX_mm: 2.8; SizeY_mm: 2.9; SizeArea_mm2: 8.12; CompType: IC; AEC Qualified: Y; AEC Category: Q200

## Sheet TIDA-050008_CAN Supply and Supervisor.SchDoc
size 431 x 279 mm; Date: Not shown in title block; ApprovedBy: Not shown in title block; CheckedBy: Not shown in title block; Author: Not shown in title block; CompanyName: Not shown in title block; Engineer: Not shown in title block; Organization: Not shown in title block; Address1: Not shown in title block; Address2: Not shown in title block; Address3: Not shown in title block; Address4: Not shown in title block; DocumentNumber: 4; Revision: Use project parameter SCH_Rev; SheetNumber: 4; SheetTotal: 6; PageSetup: Record=PageOptions¦CenterHorizontal=True¦CenterVertical=True¦PrintScale=1.00¦XCorrection=1.00¦YCorrection=1.00¦PrintKind=0¦BorderSize=5000000¦LeftOffset=0¦BottomOffset=0¦Orientation=2¦PaperLength=1000¦PaperWidth=1000¦Scale=100¦PaperSource=15¦PrintQuality=600¦MediaType=1¦DitherType=10¦PaperKind=Letter¦PrintScaleMode=1
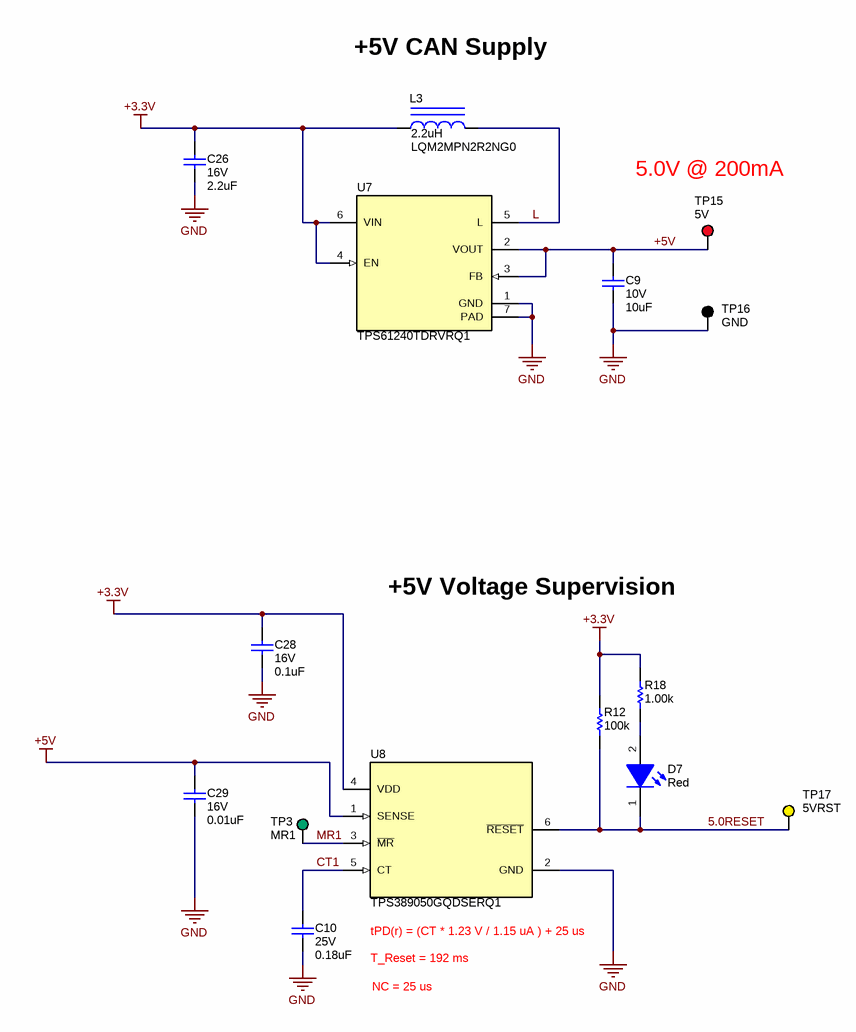
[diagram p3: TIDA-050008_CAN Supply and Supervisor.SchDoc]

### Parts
C9  VDC_V: 10V  ValueDisplayed: 10uF  [0603]  (hidden comment: GRM188Z71A106MA73D)
C10  VDC_V: 25V  ValueDisplayed: 0.18uF  [0603]  (hidden comment: GRM188R71E184KA88D)
C26  VDC_V: 16V  ValueDisplayed: 2.2uF  [0603]  (hidden comment: GRM188Z71C225KE43)
C28  VDC_V: 16V  ValueDisplayed: 0.1uF  [0603]  (hidden comment: GRM188R71C104KA01D)
C29  VDC_V: 16V  ValueDisplayed: 0.01uF  [0603]  (hidden comment: GRM188R71C103KA01D)
D7  value Red  [SML-P1_RED]  (hidden comment: SML-P12UTT86)
L3  LQM2MPN2R2NG0  ValueDisplayed: 2.2uH  [LQM2MPN_G0]
R12  ValueDisplayed: 100k  [0603]  (hidden comment: CRCW0603100KFKEA)
R18  ValueDisplayed: 1.00k  [0402]  (hidden comment: CRCW04021K00FKED)
TP3  MR1  [Keystone5126]
TP15  5V  [Keystone5010]
TP16  GND  [Keystone5011]
TP17  5VRST  [Keystone5014]
U7  TPS61240TDRVRQ1  [DRV0006A]
U8  TPS389050GQDSERQ1  [DSE0006A]

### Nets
+3.3V: C26.1 C28.1 L3.1 R12.2 R18.1 U7.4(EN) U7.6(VIN) U8.4(VDD)
+5V: C9.2 C29.1 TP15.1 U7.2(VOUT) U7.3(FB) U8.1(SENSE)
GND: C9.1 C10.2 C26.2 C28.2 C29.2 TP16.1 U7.1(GND) U7.7(PAD) U8.2(GND)
5.0RESET: D7.1(K) R12.1 TP17.1 U8.6(~{RESET})
CT1: C10.1 U8.5(CT)
L: L3.2 U7.5(L)
MR1: TP3.1 U8.3(~{MR})
NetD7_2: D7.2(A) R18.2

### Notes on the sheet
- +5V CAN Supply
- 5.0V @ 200mA
- +5V Voltage Supervision
- tPD(r) = (CT * 1.23 V / 1.15 uA ) + 25 us
- NC = 25 us
- T_Reset = 192 ms

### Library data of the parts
C9 = CMP-0007497-5: CAP, CERM, 10 uF, 10 V, +/- 20%, X7R, 0603; Manufacturer: MuRata; TaMin_C: -55°C; Polarized: N; SizeAreaWB_mm2: 4.68; Value1: Unknown; U/M: EA; Value: 10uF; TaMax_C: 125°C; SizeZ_mm: 1; SizeX_mm: 1.6; SizeY_mm: 0.8; SizeArea_mm2: 1.28; Cap_F: 10µF; AEC Category: Q200
C10 = CMP-0007413-4: CAP, CERM, 0.18 uF, 25 V, +/- 10%, X7R, 0603; Manufacturer: MuRata; TaMin_C: -55°C; Polarized: N; SizeAreaWB_mm2: 4.68; Value1: Unknown; U/M: EA; Value: 0.18uF; TaMax_C: 125°C; SizeZ_mm: 1; SizeX_mm: 1.6; SizeY_mm: 0.8; SizeArea_mm2: 1.28; Cap_F: 180nF; AEC Category: Q200
C26 = CMP-0007499-4: as C15 on sheet TIDA-050008_Watchdog and Vref
C28 = CMP-0007378-5: CAP, CERM, 0.1 uF, 16 V, +/- 10%, X7R, 0603; Manufacturer: MuRata; TaMin_C: -55°C; Polarized: N; SizeAreaWB_mm2: 4.68; Value1: Unknown; U/M: EA; Value: 0.1uF; TaMax_C: 125°C; SizeZ_mm: 1; SizeX_mm: 1.6; SizeY_mm: 0.8; SizeArea_mm2: 1.28; CompType: Capacitor; AEC Category: Q200; Cap_F: 100nF
C29 = CMP-0007377-4: CAP, CERM, 0.01 uF, 16 V, +/- 10%, X7R, 0603; Manufacturer: MuRata; TaMin_C: -55°C; Polarized: N; SizeAreaWB_mm2: 4.68; Value1: Unknown; U/M: EA; Value: 0.01uF; TaMax_C: 125°C; SizeZ_mm: 1; SizeX_mm: 1.6; SizeY_mm: 0.8; SizeArea_mm2: 1.28; CompType: Capacitor; Cap_F: 10nF; AEC Category: Q200
D7 = CMP-0002872-1: as D2 on sheet TIDA-050008_Main Supply
L3 = CMP-0058761-1: Inductor, Multilayer, Ferrite, 2.2 uH, 1.2 A, 0.11 ohm, SMD; Manufacturer: MuRata; Irms: 1.2A @ 40C rise; SizeAreaWB_mm2: 7.8; DCR_ohm: 1.1d; Value: 2.2uH; Imax_A: 1.2A; SizeZ_mm: 1; SizeX_mm: 2; SizeY_mm: 1.6; SizeArea_mm2: 3.2; Ind_H: 2.2µH; AEC Qualified: N; AEC Category: Q200
R12 = CMP-0021990-4: as RFBT on sheet TIDA-050008_Main Supply
R18 = CMP-0026071-3: as R15 on sheet TIDA-050008_Watchdog and Vref
TP3 = CMP-0055158-1: Test Point, Multipurpose, Green, TH; Manufacturer: Keystone; PartNumber: 5126; CNHeader: FALSE; Green_Lifecycle: Active; Green_REACh: Passed; ContactFinish: Silver; CT: TRUE
TP15 = CMP-0055147-1: as TP2 on sheet TIDA-050008_Main Supply
TP16 = CMP-0055148-1: Test Point, Multipurpose, Black, TH; Manufacturer: Keystone; PartNumber: 5011; CNHeader: FALSE; Green_Lifecycle: Active; Green_REACh: Passed; ContactFinish: Silver; CT: TRUE
TP17 = CMP-0055151-1: as TP6 on sheet TIDA-050008_Watchdog and Vref
U7 = CMP-0065188-6: 3.5-MHz High Efficiency Step-Up Converter, DRV0006A (WSON-6); Manufacturer: Texas Instruments; SizeX_mm: 2; CompType: IC; SizeZ_mm: 0.8; SizeArea_mm2: 4; SizeAreaWB_mm2: 9; U/M: EA
U8 = CMP-0081405-1: Automotive Low-Quiescent-Current 1% Accurate Supervisor With Programmable Delay, DSE0006A (WSON-6); Alternate Manufacturer: Texas Instruments; SizeAreaWB_mm2: 6.25; SizeZ_mm: 0.8; SizeX_mm: 1.5; SizeArea_mm2: 2.25; CompType: IC; AEC Qualified: Y; AEC Category: Q200

## Sheet TIDA-050008 Core Supply and Supervisor.SchDoc
size 431 x 279 mm; Date: Not shown in title block; ApprovedBy: Not shown in title block; CheckedBy: Not shown in title block; Author: Not shown in title block; CompanyName: Not shown in title block; Engineer: Not shown in title block; Organization: Not shown in title block; Address1: Not shown in title block; Address2: Not shown in title block; Address3: Not shown in title block; Address4: Not shown in title block; DocumentNumber: 5; Revision: Use project parameter SCH_Rev; SheetNumber: 5; SheetTotal: 6; PageSetup: Record=PageOptions¦CenterHorizontal=True¦CenterVertical=True¦PrintScale=1.00¦XCorrection=1.00¦YCorrection=1.00¦PrintKind=0¦BorderSize=5000000¦LeftOffset=0¦BottomOffset=0¦Orientation=2¦PaperLength=1000¦PaperWidth=1000¦Scale=100¦PaperSource=15¦PrintQuality=600¦MediaType=1¦DitherType=10¦PaperKind=Letter¦PrintScaleMode=1
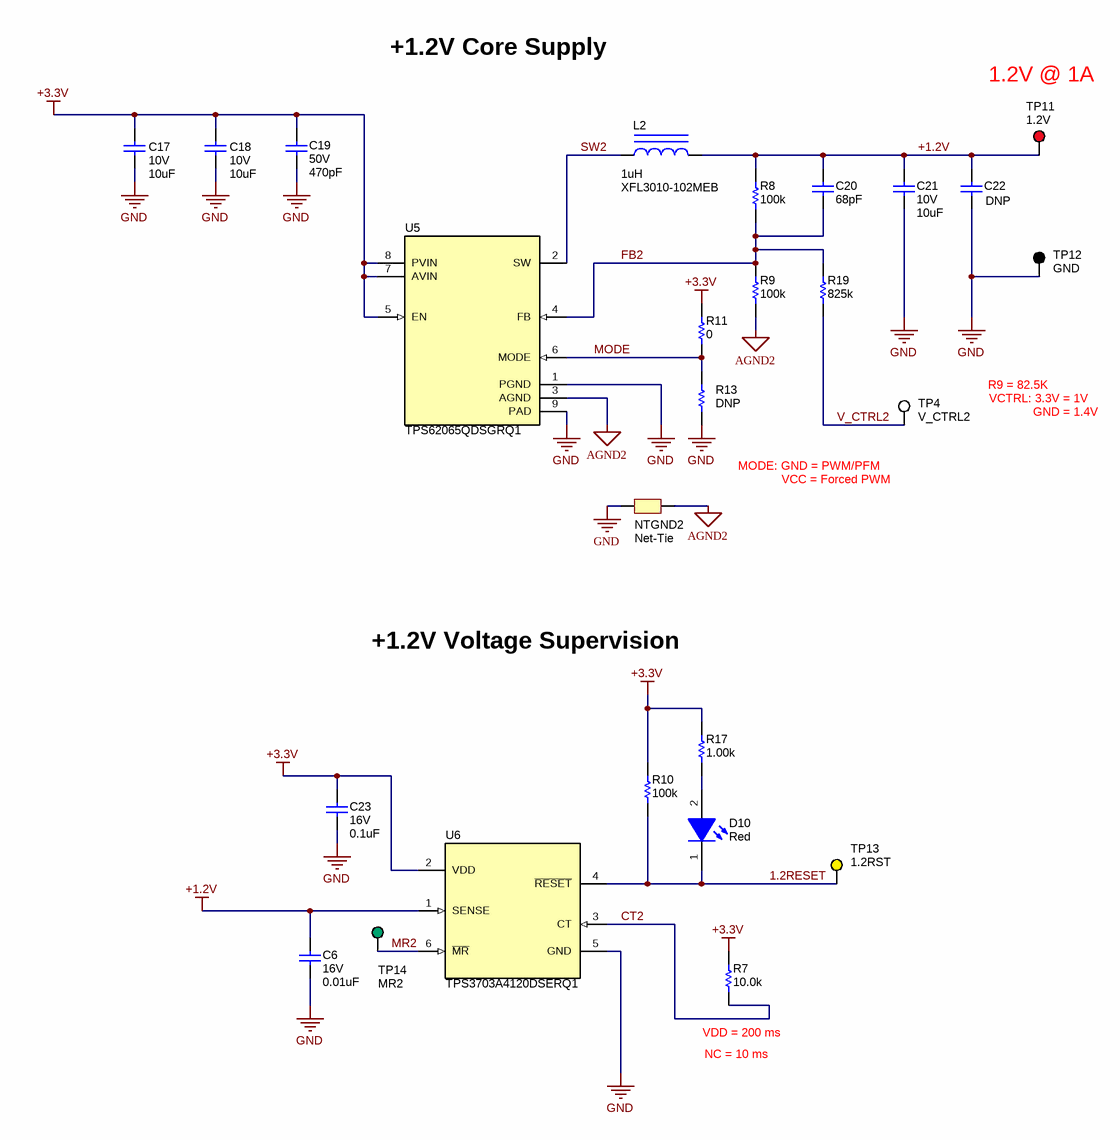
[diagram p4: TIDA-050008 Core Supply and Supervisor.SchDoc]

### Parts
C6  VDC_V: 16V  ValueDisplayed: 0.01uF  [0603]  (hidden comment: GRM188R71C103KA01D)
C17  Value2: 10V  ValueDisplayed: 10uF  [0603L]  (hidden comment: GRM188Z71A106MA73D)
C18  Value2: 10V  ValueDisplayed: 10uF  [0603L]  (hidden comment: GRM188Z71A106MA73D)
C19  VDC_V: 50V  ValueDisplayed: 470pF  [0402]  (hidden comment: GCM155R71H471KA37D)
C20  ValueDisplayed: 68pF  [0402]  (hidden comment: C1005C0G1H680J050BA)
C21  VDC_V: 10V  ValueDisplayed: 10uF  [0603]  (hidden comment: GRM188Z71A106MA73D)
C22  DNP  [0603]
C23  VDC_V: 16V  ValueDisplayed: 0.1uF  [0603L]  (hidden comment: GRM188R71C104KA01D)
D10  value Red  [SML-P1_RED]  (hidden comment: SML-P12UTT86)
L2  ValueDisplayed: 1uH  [XFL3010]  (hidden comment: XFL3010-102MEB)
NTGND2  Net-Tie  [Net-Tie_10mil]  (net tie, no BOM)
R7  ValueDisplayed: 10.0k  [0603]  (hidden comment: CRCW060310K0FKEA)
R8  ValueDisplayed: 100k  [0603]  (hidden comment: CRCW0603100KFKEA)
R9  ValueDisplayed: 100k  [0603]  (hidden comment: CRCW0603100KFKEA)
R10  ValueDisplayed: 100k  [0603]  (hidden comment: CRCW0603100KFKEA)
R11  ValueDisplayed: 0  [0603]  (hidden comment: CRCW06030000Z0EA)
R13  DNP  [0603]
R17  ValueDisplayed: 1.00k  [0402]  (hidden comment: CRCW04021K00FKED)
R19  ValueDisplayed: 825k  [0603]  (hidden comment: CRCW0603825KFKEA)
TP4  V_CTRL2  [Keystone5012]
TP11  1.2V  [Keystone5010]
TP12  GND  [Keystone5011]
TP13  1.2RST  [Keystone5014]
TP14  MR2  [Keystone5126]
U5  TPS62065QDSGRQ1  [DSG0008A]
U6  TPS3703A4120DSERQ1  [DSE0006A]

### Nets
+1.2V: C6.1 C20.1 C21.1 C22.1 L2.2 R8.2 TP11.1 U6.1(SENSE)
+3.3V: C17.1 C18.1 C19.1 C23.1 R7.2 R10.2 R11.2 R17.1 U5.5(EN) U5.7(AVIN) U5.8(PVIN) U6.2(VDD)
AGND2: NTGND2.2 R9.1 U5.3(AGND)
GND: C6.2 C17.2 C18.2 C19.2 C21.2 C22.2 C23.2 NTGND2.1 R13.1 TP12.1 U5.1(PGND) U5.9(PAD) U6.5(GND)
1.2RESET: D10.1(K) R10.1 TP13.1 U6.4(~{RESET})
CT2: R7.1 U6.3(CT)
FB2: C20.2 R8.1 R9.2 R19.2 U5.4(FB)
MODE: R11.1 R13.2 U5.6(MODE)
MR2: TP14.1 U6.6(~{MR})
SW2: L2.1 U5.2(SW)
V_CTRL2: R19.1 TP4.1
NetD10_2: D10.2(A) R17.2

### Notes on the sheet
- +1.2V Core Supply
- 1.2V @ 1A
- R9 = 82.5K
- VCTRL: 3.3V = 1V
- GND = 1.4V
- MODE: GND = PWM/PFM
- VCC = Forced PWM
- +1.2V Voltage Supervision
- (near R7) VDD = 200 ms
- NC = 10 ms

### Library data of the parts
C6 = CMP-0007377-4: as C29 on sheet TIDA-050008_CAN Supply and Supervisor
C17 C18 = CMP-0007497-5: CAP, CERM, 10 uF, 10 V, +/- 20%, X7R, 0603; Manufacturer: MuRata; TaMin_C: -55°C; Polarized: N; SizeAreaWB_mm2: 4.68; Value1: Unknown; U/M: EA; Value: 10uF; TaMax_C: 125°C; SizeZ_mm: 1; SizeX_mm: 1.6; SizeY_mm: 0.8; Cap_Case: 0603; SizeArea_mm2: 1.28; CompType: Capacitor; Cap_F: 10µF; AEC Category: Q200
C19 = CMP-0006360-2: CAP, CERM, 470 pF, 50 V, +/- 10%, X7R, AEC-Q200 Grade 1, 0402; Manufacturer: MuRata; TaMin_C: -55°C; Polarized: N; SizeAreaWB_mm2: 3; Value1: Unknown; U/M: EA; Value: 470pF; TaMax_C: 125°C; SizeZ_mm: 0.6; SizeX_mm: 1; SizeY_mm: 0.5; AEC Qualified: Y; AEC Category: Q200
C20 = CMP-0006251-2: CAP, CERM, 68 pF, 50 V, +/- 5%, C0G/NP0, 0402; Manufacturer: TDK; Polarized: N; CompType: Capacitor; Value: 68pF; U/M: EA; Value1: Unknown; VDC_V: 50V; TaMin_C: -55°C; TaMax_C: 125°C; SizeArea_mm2: 0.5; SizeAreaWB_mm2: 3; SizeX_mm: 1; SizeZ_mm: 0.6; AEC Category: Q200
C21 = CMP-0007497-5: as C9 on sheet TIDA-050008_CAN Supply and Supervisor
C22 = CMP-0007158-5: CAP, CERM, 22 uF, 10 V, +/- 20%, X5R, 0603; Manufacturer: MuRata; PartNumber: GRM187R61A226ME15D; TaMin_C: -55°C; Polarized: N; SizeAreaWB_mm2: 4.68; Value1: Unknown; U/M: EA; Value: 22uF; TaMax_C: 85°C; SizeZ_mm: 1; SizeX_mm: 1.6; SizeY_mm: 0.8; Value2: 10V; SizeArea_mm2: 1.28; CompType: Capacitor; Cap_F: 22µF; AEC Category: Q200
C23 = CMP-0007378-5: CAP, CERM, 0.1 uF, 16 V, +/- 10%, X7R, 0603; Manufacturer: MuRata; TaMin_C: -55°C; Polarized: N; SizeAreaWB_mm2: 4.68; Value1: Unknown; U/M: EA; Value: 0.1uF; TaMax_C: 125°C; SizeZ_mm: 1; SizeX_mm: 1.6; SizeY_mm: 0.8; Cap_Case: 0603; SizeArea_mm2: 1.28; CompType: Capacitor; AEC Category: Q200; Cap_F: 100nF
D10 = CMP-0002872-1: as D2 on sheet TIDA-050008_Main Supply
L2 = CMP-0061128-1: Inductor, Shielded, Composite, 1 uH, 2.3 A, 0.04 ohm, SMD; Manufacturer: Coilcraft; Isat: 2.4A @ 30% inductance drop; Irms: 2.3A @ 40C rise; Green_Lifecycle: Not Set; SizeAreaWB_mm2: 16; DCR_ohm: 0.04; Green_REACh: Incomplete; Value: 1uH; Imax_A: 2.3A; SizeZ_mm: 1; SizeX_mm: 3; SizeArea_mm2: 9; Ind_H: 1µH; AEC Category: Q200
NTGND2 = Net-Tie: as NTGND1 on sheet TIDA-050008_Main Supply
R7 = CMP-0021998-4: RES, 10.0 k, 1%, 0.1 W, AEC-Q200 Grade 0, 0603; Manufacturer: Vishay-Dale; Value: 10.0k; Res_ohm: 10k; Value_Code: 10k0; Power_W: 100mW; Value2: 0.1W; VDC_V: 75V; TempCo: 100 ppm/C; SizeArea_mm2: 1.28; SizeX_mm: 1.6; SizeY_mm: 0.8; SizeZ_mm: 1; EIA_Code: E96; AEC Category: Q200; AEC Qualified: Y; AEC Grade: 0
R8-R10 = CMP-0021990-4: as RFBT on sheet TIDA-050008_Main Supply
R11 R13 = CRCW06030000Z0EA: RES, 0, 5%, 0.1 W, 0603; Manufacturer: Vishay-Dale; CompType: Resistor; Value: 0; Value_Code: 0000; Tolerance_%: 5; Power_W: 0.1; Value2: 0.1W; VDC_V: 75; TempCo: 200 ppm/C; SizeArea_mm2: 1.28; SizeX_mm: 1.6; SizeY_mm: 0.8; SizeZ_mm: 1; EIA_Code: E24; U/M: EA; AEC Category: Q200; Green_Lifecycle: Active; Green_REACh: Passed
R17 = CMP-0026071-3: as R15 on sheet TIDA-050008_Watchdog and Vref
R19 = CMP-0022618-3: RES, 825 k, 1%, 0.1 W, AEC-Q200 Grade 0, 0603; Manufacturer: Vishay-Dale; Value: 825k; Power_W: 100mW; Value2: 0.1W; VDC_V: 75V; TempCo: 100 ppm/C; SizeArea_mm2: 1.28; SizeX_mm: 1.6; SizeY_mm: 0.8; SizeZ_mm: 1; EIA_Code: E96; AEC Category: Q200; AEC Qualified: Y; AEC Grade: 0
TP4 = CMP-0055149-1: Test Point, Multipurpose, White, TH; Manufacturer: Keystone; CNHeader: FALSE; Green_Lifecycle: Active; Green_REACh: Passed; ContactFinish: Silver; CT: TRUE
TP11 = CMP-0055147-1: as TP2 on sheet TIDA-050008_Main Supply
TP12 = CMP-0055148-1: as TP16 on sheet TIDA-050008_CAN Supply and Supervisor
TP13 = CMP-0055151-1: as TP6 on sheet TIDA-050008_Watchdog and Vref
TP14 = CMP-0055158-1: as TP3 on sheet TIDA-050008_CAN Supply and Supervisor
U5 = CMP-0074019-3: 3MHz, 2A Automotive Step-Down Converter in 2x2 SON Package, DSG0008A (WSON-8); Manufacturer: Texas Instruments; SizeZ_mm: 0.8; SizeX_mm: 2.0; SizeArea_mm2: 4.0; CompType: IC; SizeAreaWB_mm2: 9.0; AEC Category: Q200; AEC Qualified: Y
U6 = CMP-0081404-1: Automotive High-Accuracy Window Supervisor With Reset Time Delay and Manual Reset, DSE0006A (WSON-6); Alternate Manufacturer: Texas Instruments; SizeAreaWB_mm2: 6.25; SizeZ_mm: 0.8; SizeX_mm: 1.5; SizeArea_mm2: 2.25; CompType: IC; AEC Qualified: Y; AEC Category: Q200

## Sheet TIDA-050008_EVM_Hardware.SchDoc
size 431 x 279 mm; Date: Not shown in title block; ApprovedBy: Not shown in title block; CheckedBy: Not shown in title block; Author: Not shown in title block; CompanyName: Not shown in title block; Engineer: Not shown in title block; Organization: Not shown in title block; Address1: Not shown in title block; Address2: Not shown in title block; Address3: Not shown in title block; Address4: Not shown in title block; DocumentNumber: 6; Revision: Use project parameter SCH_Rev; SheetNumber: 6; SheetTotal: 6; PageSetup: Record=PageOptions¦CenterHorizontal=True¦CenterVertical=True¦PrintScale=1.00¦XCorrection=1.00¦YCorrection=1.00¦PrintKind=0¦BorderSize=5000000¦LeftOffset=0¦BottomOffset=0¦Orientation=2¦PaperLength=1000¦PaperWidth=1000¦Scale=100¦PaperSource=15¦PrintQuality=600¦MediaType=1¦DitherType=10¦PaperKind=Letter¦PrintScaleMode=1
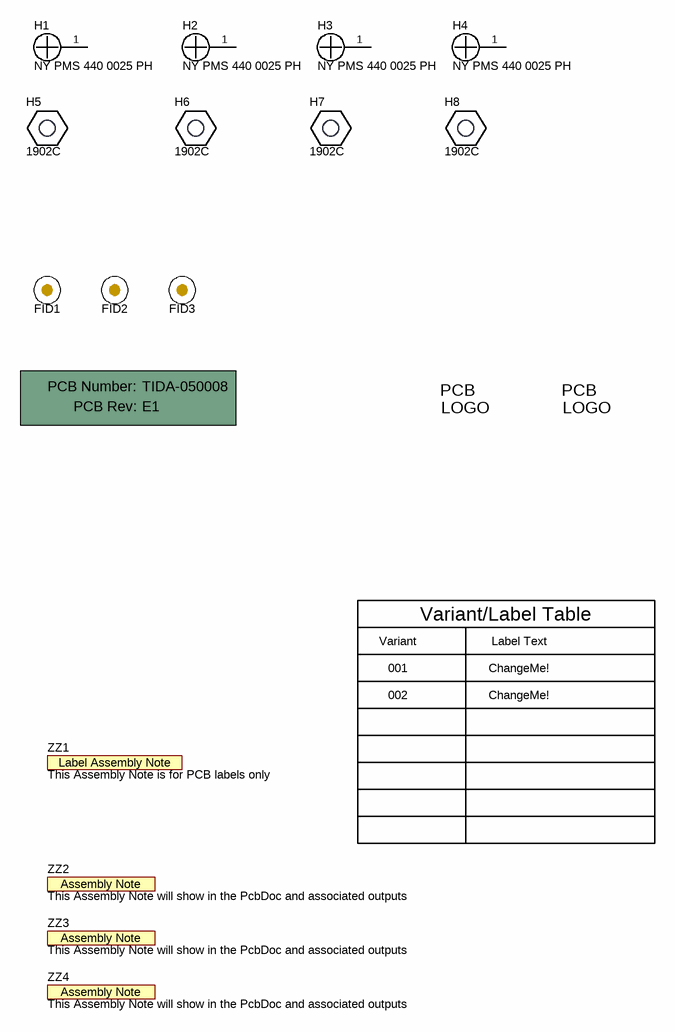
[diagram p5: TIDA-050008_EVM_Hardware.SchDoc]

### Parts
!PCB1  Printed Circuit Board  (value not drawn)  (mechanical)
FID1  Fiducial  [Fiducial10-20]  (value not drawn)
FID2  Fiducial  [Fiducial10-20]  (value not drawn)
FID3  Fiducial  [Fiducial10-20]  (value not drawn)
H1  NY PMS 440 0025 PH  [NY PMS 440 0025 PH]
H2  NY PMS 440 0025 PH  [NY PMS 440 0025 PH]
H3  NY PMS 440 0025 PH  [NY PMS 440 0025 PH]
H4  NY PMS 440 0025 PH  [NY PMS 440 0025 PH]
H5  1902C  [Keystone_1902C]
H6  1902C  [Keystone_1902C]
H7  1902C  [Keystone_1902C]
H8  1902C  [Keystone_1902C]
Logo2  Pb-Free Symbol  [Pb-Free_Overlay_Small]  (value not drawn)  (no BOM)
Logo3  FCC disclaimer  [FCC_disclaimer]  (value not drawn)  (no BOM)
ZZ1  This Assembly Note is for PCB labels only  [AssemblyNoteLabel]  (no BOM)
ZZ2  This Assembly Note will show in the PcbDoc and associated outputs  [AssemblyNote]  (no BOM)
ZZ3  This Assembly Note will show in the PcbDoc and associated outputs  [AssemblyNote]  (no BOM)
ZZ4  This Assembly Note will show in the PcbDoc and associated outputs  [AssemblyNote]  (no BOM)

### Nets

Not connected (* = marked no-connect by the designer): H1 1; H2 1; H3 1; H4 1

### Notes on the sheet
- Variant
- Variant/Label Table
- Label Text
- 001
- 002
- ChangeMe!

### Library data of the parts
!PCB1 = PCB: Manufacturer: Any; PartNumber: TIDA-050008; SymbolCreator: a0412235
FID1-FID3 = Fiducial: Fiducial mark.  There is nothing to buy or mount.; SymbolCreator: codlsc
H1-H4 = NY PMS 440 0025 PH: Machine Screw, Round, #4-40 x 1/4, Nylon, Philips panhead; Manufacturer: B&F Fastener Supply; CompType: Hardware; SymbolCreator: codlsc; U/M: EA; Green_Lifecycle: Not Set; Green_REACh: Incomplete
H5-H8 = 1902C: Standoff, Hex, 0.5"L #4-40 Nylon; Manufacturer: Keystone; Green_Lifecycle: Active; Green_REACh: Passed; SymbolCreator: a0412235
Logo2 = Pb-Free: SymbolCreator: a0412235
Logo3 = FCC_disclaimer: SymbolCreator: a0412235
ZZ1 = AssemblyNoteLabel: SymbolCreator: a0412235
ZZ2-ZZ4 = AssemblyNote: SymbolCreator: codlsc

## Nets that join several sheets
+3.3V: TIDA-050008_Main Supply (13 pins), TIDA-050008_Watchdog and Vref (14 pins), TIDA-050008_CAN Supply and Supervisor (8 pins), TIDA-050008 Core Supply and Supervisor (12 pins)
GND: TIDA-050008_Main Supply (44 pins), TIDA-050008_Watchdog and Vref (10 pins), TIDA-050008_CAN Supply and Supervisor (9 pins), TIDA-050008 Core Supply and Supervisor (13 pins)

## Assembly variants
001: not fitted C12 C22 FID1 FID2 FID3 R7 R13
